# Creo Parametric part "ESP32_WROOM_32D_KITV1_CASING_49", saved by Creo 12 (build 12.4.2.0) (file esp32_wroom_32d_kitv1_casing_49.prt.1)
Units: Custom; MM, KILOGRAM, SECS

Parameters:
  PTC_WM_ITERATION = "0"
  PTC_WM_VERSION = "-.0"
  PTC_WM_LIFECYCLE_STATE = "In Work"
  PTC_WM_LIFECYCLE = "MO_CADDocument"
  PTC_WM_CREATED_BY = "Maximilian Roepper (Z0017RMS: MO)"
  PTC_WM_CREATED_ON = "18-Sep-26 11:36:42 AM"
  PTC_WM_MODIFIED_BY = "Maximilian Roepper (Z0017RMS: MO)"
  PTC_WM_MODIFIED_ON = "18-Sep-26 11:36:46 AM"
  PDMLINKNUMBER = "PDM000071454980"
  PTC_WM_NAME = "esp32_wroom_32d_kitv1_casing_49.prt"
  PTC_WM_NUMBER = "PDM000071454980"

Other parameters: WEIGHT, WEIGHT_FACTOR, WEIGHT_ADD, _MASS_TEMP, _DIFF_TEMP, MC_ERRORS, SUPPLIER

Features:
  1. coordinate system
  2. datum plane "PRT_YZ"
  3. datum plane "PRT_XY"
  4. datum plane "PRT_XZ"
  5. coordinate system
  6. datum axis
  7. datum axis
  8. datum axis
  9. coordinate system
  10. imported feature
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
Other named items: PRT, SIEMENS_MO, DRW_VIEW_ORG, PRT_X, PRT_Y, PRT_Z, CS0, ROUGH_GROB

Layers: 00_STD_CSYS-KSYS, 01_STD_PLANES-EBENEN, 02_STD_AXES-ACHSEN, 03_STD_CSYS-KSYS, 24_IMPORT_FEAT-IMPORT_KE

Surfaces: 6 plane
